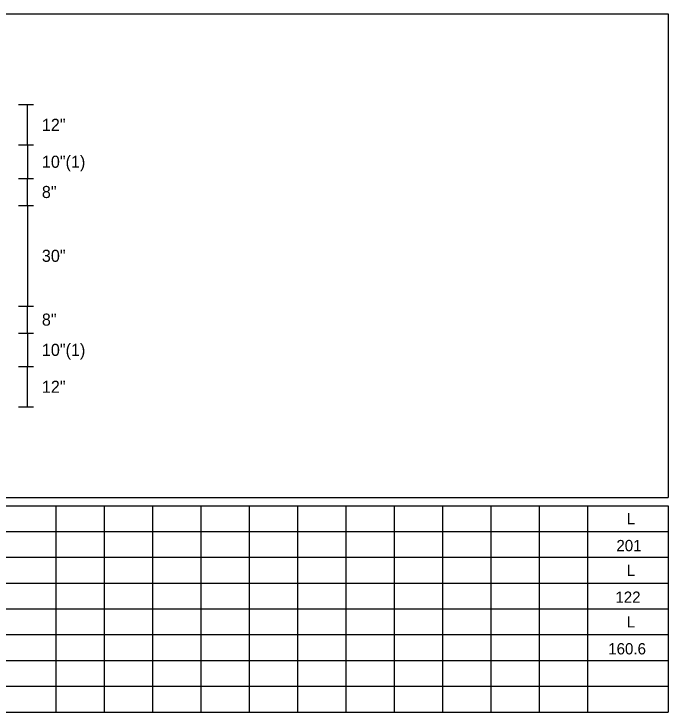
# Model space of a CAD drawing. Extents: x 10268312 to 10268471, y 2141099 to 2141204.
# Drawn here: x 10268430.39 to 10268470.98, y 2141160.23 to 2141203.53 of the extents above; entities that cross this region are included whole.
import ezdxf

# ---------------------------------------------------------------- set-up
doc = ezdxf.new("R2010")
doc.units = 0
for name, color, linetype in [('GSDims', 7, 'Continuous'), ('SumBoxLines_dp', 7, 'Continuous'), ('SumBoxLinesMin_dp', 7, 'Continuous'), ('TextLabel', 7, 'Continuous')]:
    doc.layers.add(name, color=color, linetype=linetype)

msp = doc.modelspace()

# ---------------------------------------------------------------- linework, layer by layer
at = {"layer": 'GSDims'}
for p, q in [((10268430.668, 2141197.903), (10268431.605, 2141197.903)), ((10268431.23, 2141195.403), (10268431.23, 2141197.903)), ((10268430.668, 2141195.403), (10268431.605, 2141195.403)), ((10268430.668, 2141195.403), (10268431.605, 2141195.403)), ((10268431.23, 2141195.403), (10268431.23, 2141193.32)), ((10268430.668, 2141193.32), (10268431.605, 2141193.32)), ((10268430.668, 2141193.32), (10268431.605, 2141193.32)), ((10268431.23, 2141191.653), (10268431.23, 2141193.32)), ((10268430.668, 2141191.653), (10268431.605, 2141191.653)), ((10268431.23, 2141191.653), (10268431.23, 2141185.403)), ((10268430.668, 2141185.403), (10268431.605, 2141185.403)), ((10268431.23, 2141183.737), (10268431.23, 2141185.403)), ((10268430.668, 2141183.737), (10268431.605, 2141183.737)), ((10268430.668, 2141183.737), (10268431.605, 2141183.737)), ((10268431.23, 2141183.737), (10268431.23, 2141181.653)), ((10268430.668, 2141181.653), (10268431.605, 2141181.653)), ((10268430.668, 2141181.653), (10268431.605, 2141181.653)), ((10268431.23, 2141179.153), (10268431.23, 2141181.653)), ((10268430.668, 2141179.153), (10268431.605, 2141179.153))]:
    msp.add_line(p, q, dxfattribs=at)
at = {"layer": 'SumBoxLines_dp'}
for p, q in [((10268341.73, 2141203.528), (10268470.98, 2141203.528)), ((10268470.98, 2141203.528), (10268470.98, 2141173.528)), ((10268341.73, 2141173.528), (10268470.98, 2141173.528)), ((10268318.48, 2141173.028), (10268470.98, 2141173.028)), ((10268432.98, 2141173.028), (10268432.98, 2141170.642)), ((10268435.98, 2141173.028), (10268435.98, 2141160.228)), ((10268438.98, 2141173.028), (10268438.98, 2141163.428)), ((10268441.98, 2141173.028), (10268441.98, 2141160.228)), ((10268444.98, 2141173.028), (10268444.98, 2141160.228)), ((10268447.98, 2141173.028), (10268447.98, 2141160.228)), ((10268450.98, 2141173.028), (10268450.98, 2141160.228)), ((10268453.98, 2141173.028), (10268453.98, 2141170.642)), ((10268456.98, 2141173.028), (10268456.98, 2141160.228)), ((10268459.98, 2141173.028), (10268459.98, 2141163.428)), ((10268462.98, 2141173.028), (10268462.98, 2141160.228)), ((10268465.98, 2141173.028), (10268465.98, 2141160.228)), ((10268470.98, 2141173.028), (10268470.98, 2141160.228)), ((10268432.98, 2141170.642), (10268432.98, 2141160.228)), ((10268453.98, 2141170.642), (10268453.98, 2141160.228)), ((10268318.48, 2141169.828), (10268470.98, 2141169.828)), ((10268318.48, 2141166.628), (10268470.98, 2141166.628)), ((10268318.48, 2141163.428), (10268470.98, 2141163.428)), ((10268438.98, 2141163.428), (10268438.98, 2141160.228)), ((10268459.98, 2141163.428), (10268459.98, 2141160.228)), ((10268318.48, 2141160.228), (10268470.98, 2141160.228))]:
    msp.add_line(p, q, dxfattribs=at)
at = {"layer": 'SumBoxLinesMin_dp'}
for p, q in [((10268318.48, 2141171.428), (10268470.98, 2141171.428)), ((10268318.48, 2141168.228), (10268470.98, 2141168.228)), ((10268318.48, 2141165.028), (10268470.98, 2141165.028)), ((10268318.48, 2141161.828), (10268470.98, 2141161.828))]:
    msp.add_line(p, q, dxfattribs=at)

# ---------------------------------------------------------------- texts
at = {"layer": 'GSDims'}
for s, p in [('12"', (10268432.119, 2141196.278)), ('10"(1)', (10268432.119, 2141193.987)), ('8"', (10268432.119, 2141192.112)), ('30"', (10268432.119, 2141188.153)), ('8"', (10268432.119, 2141184.195)), ('10"(1)', (10268432.119, 2141182.32)), ('12"', (10268432.119, 2141180.028))]:
    msp.add_text(s, height=0.75, dxfattribs=at).set_placement(p)
at = {"layer": 'TextLabel'}
for s, p in [('L', (10268468.411, 2141171.873)), ('201', (10268467.775, 2141170.203)), ('L', (10268468.411, 2141168.673)), ('122', (10268467.712, 2141167.003)), ('L', (10268468.411, 2141165.473)), ('160.6', (10268467.267, 2141163.803))]:
    msp.add_text(s, height=0.7, dxfattribs=at).set_placement(p)

doc.saveas('drawing.dxf')
